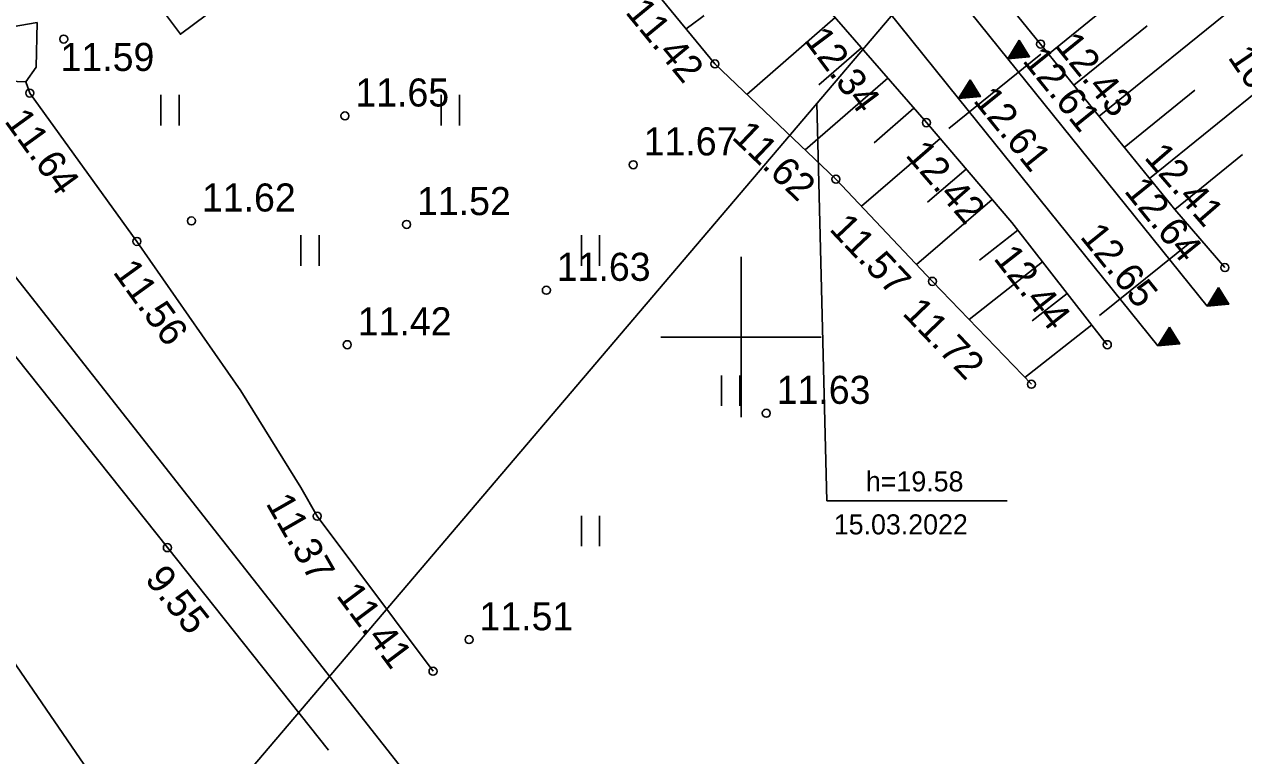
# Model space of a CAD drawing. Extents: x 554198 to 554371, y 6593448 to 6593563.
# Drawn here: x 554282.11 to 554312.55, y 6593489.56 to 6593507.8 of the extents above; entities that cross this region are included whole.
import ezdxf

# ---------------------------------------------------------------- set-up
doc = ezdxf.new("R2010")
doc.units = 0
for name, color, linetype in [('HALJASTUS', 7, 'Continuous'), ('KORGUS-EH2000', 7, 'Continuous'), ('PIIR', 7, 'Continuous'), ('RAJATIS', 7, 'Continuous'), ('RDT', 7, 'Continuous'), ('RELJEEF', 7, 'Continuous'), ('SIOHULIIN', 7, 'Continuous'), ('TEE', 7, 'Continuous'), ('VEEKOGU', 7, 'Continuous'), ('VORK', 7, 'Continuous')]:
    doc.layers.add(name, color=color, linetype=linetype)

msp = doc.modelspace()

# ---------------------------------------------------------------- linework, layer by layer
at = {"layer": 'HALJASTUS'}
for p, q in [((554285.514, 6593506.042), (554285.514, 6593505.28)), ((554285.97, 6593506.042), (554285.97, 6593505.28)), ((554292.514, 6593506.042), (554292.514, 6593505.28)), ((554292.97, 6593506.042), (554292.97, 6593505.28)), ((554289.014, 6593502.542), (554289.014, 6593501.78)), ((554289.47, 6593502.542), (554289.47, 6593501.78)), ((554296.014, 6593502.542), (554296.014, 6593501.78)), ((554296.47, 6593502.542), (554296.47, 6593501.78)), ((554299.514, 6593499.042), (554299.514, 6593498.28)), ((554299.97, 6593499.042), (554299.97, 6593498.28)), ((554296.014, 6593495.542), (554296.014, 6593494.78)), ((554296.47, 6593495.542), (554296.47, 6593494.78))]:
    msp.add_line(p, q, dxfattribs=at)
at = {"layer": 'KORGUS-EH2000'}
for p, q in [((554306.663, 6593506.945), (554306.948, 6593507.41)), ((554306.909, 6593507.346), (554306.871, 6593506.962)), ((554306.939, 6593507.394), (554306.896, 6593506.965)), ((554306.963, 6593507.387), (554306.921, 6593506.967)), ((554306.985, 6593507.351), (554306.947, 6593506.969)), ((554307.207, 6593506.991), (554306.948, 6593507.41)), ((554307.006, 6593507.316), (554306.972, 6593506.971)), ((554306.729, 6593507.052), (554306.719, 6593506.95)), ((554306.759, 6593507.101), (554306.744, 6593506.952)), ((554306.789, 6593507.15), (554306.769, 6593506.954)), ((554306.819, 6593507.199), (554306.795, 6593506.956)), ((554306.849, 6593507.248), (554306.82, 6593506.958)), ((554306.879, 6593507.297), (554306.845, 6593506.96)), ((554307.028, 6593507.281), (554306.997, 6593506.973)), ((554307.049, 6593507.246), (554307.023, 6593506.975)), ((554307.071, 6593507.211), (554307.048, 6593506.977)), ((554307.093, 6593507.176), (554307.073, 6593506.979)), ((554307.114, 6593507.141), (554307.099, 6593506.982)), ((554307.136, 6593507.106), (554307.124, 6593506.984)), ((554307.158, 6593507.07), (554307.149, 6593506.986)), ((554307.179, 6593507.035), (554307.175, 6593506.988)), ((554306.663, 6593506.945), (554307.207, 6593506.991)), ((554306.669, 6593506.955), (554306.668, 6593506.945)), ((554306.699, 6593507.003), (554306.693, 6593506.948)), ((554307.201, 6593507), (554307.2, 6593506.99)), ((554305.433, 6593505.953), (554305.718, 6593506.418)), ((554305.709, 6593506.402), (554305.666, 6593505.973)), ((554305.977, 6593505.999), (554305.718, 6593506.418)), ((554305.529, 6593506.109), (554305.514, 6593505.96)), ((554305.559, 6593506.158), (554305.539, 6593505.962)), ((554305.589, 6593506.207), (554305.565, 6593505.964)), ((554305.619, 6593506.256), (554305.59, 6593505.966)), ((554305.649, 6593506.305), (554305.615, 6593505.968)), ((554305.679, 6593506.354), (554305.641, 6593505.97)), ((554305.733, 6593506.395), (554305.691, 6593505.975)), ((554305.755, 6593506.359), (554305.717, 6593505.977)), ((554305.776, 6593506.324), (554305.742, 6593505.979)), ((554305.798, 6593506.289), (554305.767, 6593505.981)), ((554305.819, 6593506.254), (554305.793, 6593505.983)), ((554305.841, 6593506.219), (554305.818, 6593505.985)), ((554305.863, 6593506.184), (554305.843, 6593505.987)), ((554305.884, 6593506.149), (554305.869, 6593505.99)), ((554305.906, 6593506.114), (554305.894, 6593505.992)), ((554305.433, 6593505.953), (554305.977, 6593505.999)), ((554305.439, 6593505.963), (554305.438, 6593505.953)), ((554305.469, 6593506.011), (554305.463, 6593505.956)), ((554305.499, 6593506.06), (554305.489, 6593505.958)), ((554305.928, 6593506.078), (554305.919, 6593505.994)), ((554305.949, 6593506.043), (554305.945, 6593505.996)), ((554305.971, 6593506.008), (554305.97, 6593505.998)), ((554311.64, 6593500.773), (554311.925, 6593501.238)), ((554312.184, 6593500.819), (554311.925, 6593501.238)), ((554311.736, 6593500.929), (554311.721, 6593500.78)), ((554311.766, 6593500.978), (554311.746, 6593500.782)), ((554311.796, 6593501.027), (554311.772, 6593500.784)), ((554311.826, 6593501.076), (554311.797, 6593500.786)), ((554311.856, 6593501.125), (554311.822, 6593500.788)), ((554311.886, 6593501.174), (554311.848, 6593500.79)), ((554311.916, 6593501.222), (554311.873, 6593500.793)), ((554311.94, 6593501.215), (554311.898, 6593500.795)), ((554311.962, 6593501.179), (554311.924, 6593500.797)), ((554311.983, 6593501.144), (554311.949, 6593500.799)), ((554312.005, 6593501.109), (554311.974, 6593500.801)), ((554312.026, 6593501.074), (554312, 6593500.803)), ((554312.048, 6593501.039), (554312.025, 6593500.805)), ((554312.07, 6593501.004), (554312.05, 6593500.807)), ((554312.091, 6593500.969), (554312.076, 6593500.81)), ((554312.113, 6593500.934), (554312.101, 6593500.812)), ((554311.64, 6593500.773), (554312.184, 6593500.819)), ((554311.646, 6593500.783), (554311.645, 6593500.773)), ((554311.676, 6593500.831), (554311.67, 6593500.776)), ((554311.706, 6593500.88), (554311.696, 6593500.778)), ((554312.135, 6593500.898), (554312.126, 6593500.814)), ((554312.156, 6593500.863), (554312.152, 6593500.816)), ((554312.178, 6593500.828), (554312.177, 6593500.818)), ((554310.41, 6593499.781), (554310.695, 6593500.246)), ((554310.566, 6593500.035), (554310.542, 6593499.792)), ((554310.596, 6593500.084), (554310.567, 6593499.794)), ((554310.626, 6593500.133), (554310.592, 6593499.796)), ((554310.656, 6593500.182), (554310.618, 6593499.798)), ((554310.686, 6593500.23), (554310.643, 6593499.801)), ((554310.71, 6593500.223), (554310.668, 6593499.803)), ((554310.732, 6593500.187), (554310.694, 6593499.805)), ((554310.954, 6593499.827), (554310.695, 6593500.246)), ((554310.753, 6593500.152), (554310.719, 6593499.807)), ((554310.775, 6593500.117), (554310.744, 6593499.809)), ((554310.796, 6593500.082), (554310.77, 6593499.811)), ((554310.818, 6593500.047), (554310.795, 6593499.813)), ((554310.84, 6593500.012), (554310.82, 6593499.815)), ((554310.41, 6593499.781), (554310.954, 6593499.827)), ((554310.416, 6593499.791), (554310.415, 6593499.781)), ((554310.446, 6593499.839), (554310.44, 6593499.784)), ((554310.476, 6593499.888), (554310.466, 6593499.786)), ((554310.506, 6593499.937), (554310.491, 6593499.788)), ((554310.536, 6593499.986), (554310.516, 6593499.79)), ((554310.861, 6593499.977), (554310.846, 6593499.818)), ((554310.883, 6593499.942), (554310.871, 6593499.82)), ((554310.905, 6593499.906), (554310.896, 6593499.822)), ((554310.926, 6593499.871), (554310.922, 6593499.824)), ((554310.948, 6593499.836), (554310.947, 6593499.826))]:
    msp.add_line(p, q, dxfattribs=at)
for centre in [(554283.089, 6593507.435), (554307.48, 6593507.31), (554299.35, 6593506.815), (554282.242, 6593506.088), (554290.11, 6593505.52), (554304.63, 6593505.35), (554297.31, 6593504.3), (554302.37, 6593503.94), (554286.28, 6593502.9), (554291.65, 6593502.81), (554284.916, 6593502.387), (554312.081, 6593501.733), (554295.14, 6593501.17), (554304.78, 6593501.39), (554290.17, 6593499.81), (554309.146, 6593499.81), (554307.25, 6593498.822), (554300.63, 6593498.1), (554289.42, 6593495.53), (554285.677, 6593494.745), (554293.21, 6593492.45), (554292.31, 6593491.66)]:
    msp.add_circle(centre, 0.1, dxfattribs=at)
at = {"layer": 'PIIR'}
msp.add_line((554294.582, 6593485.373), (554263.353, 6593525.033), dxfattribs=at)
at = {"layer": 'RAJATIS'}
msp.add_lwpolyline([(554285.582, 6593508.122), (554285.164, 6593508.682), (554288.636, 6593511.498), (554290.603, 6593513.04), (554291.071, 6593513.244), (554290.979, 6593513.389), (554294.649, 6593516.02), (554295.41, 6593516.667), (554296.041, 6593515.909), (554296.134, 6593515.797), (554295.267, 6593515.075), (554291.81, 6593512.332), (554291.874, 6593512.238), (554291.529, 6593512.003), (554289.23, 6593510.089), (554286.977, 6593508.284), (554286.003, 6593507.557), (554285.582, 6593508.122)], dxfattribs=at)
at = {"layer": 'RDT'}
for p, q in [((554305.188, 6593505.205), (554307.485, 6593507.057)), ((554308.955, 6593500.534), (554311.251, 6593502.386))]:
    msp.add_line(p, q, dxfattribs=at)
for points in [[(554285.824, 6593532.905), (554287.956, 6593530.229), (554292.884, 6593524.093), (554297.103, 6593518.851), (554302.239, 6593512.436), (554306.663, 6593506.945), (554311.64, 6593500.773)], [(554284.588, 6593531.92), (554286.722, 6593529.242), (554291.653, 6593523.103), (554295.871, 6593517.862), (554301.007, 6593511.447), (554305.433, 6593505.953), (554310.41, 6593499.781)]]:
    msp.add_lwpolyline(points, dxfattribs=at)
at = {"layer": 'RELJEEF'}
for p, q in [((554307.68, 6593507.063), (554311.413, 6593510.089)), ((554301.135, 6593509.56), (554298.633, 6593507.688)), ((554308.94, 6593505.51), (554312.527, 6593508.418)), ((554302.349, 6593507.972), (554300.147, 6593506.056)), ((554308.31, 6593506.286), (554310.137, 6593507.767)), ((554303.006, 6593507.217), (554301.94, 6593506.29)), ((554310.199, 6593503.956), (554313.655, 6593506.758)), ((554303.662, 6593506.463), (554301.602, 6593504.671)), ((554309.57, 6593504.733), (554311.33, 6593506.16)), ((554304.318, 6593505.708), (554303.324, 6593504.843)), ((554304.971, 6593504.951), (554303.005, 6593503.269)), ((554310.829, 6593503.179), (554312.524, 6593504.554)), ((554305.621, 6593504.191), (554304.657, 6593503.366)), ((554306.271, 6593503.431), (554304.38, 6593501.813)), ((554306.913, 6593502.664), (554305.955, 6593501.915)), ((554307.529, 6593501.877), (554305.693, 6593500.441)), ((554308.145, 6593501.089), (554307.268, 6593500.403)), ((554308.761, 6593500.302), (554307.087, 6593498.992))]:
    msp.add_line(p, q, dxfattribs=at)
for points in [[(554312.081, 6593501.733), (554310.829, 6593503.179), (554307.48, 6593507.31), (554304.034, 6593511.56), (554302.88, 6593513.07), (554299.553, 6593517.378), (554298.943, 6593517.994)], [(554309.146, 6593499.81), (554306.76, 6593502.86), (554304.63, 6593505.35), (554302.161, 6593508.188), (554298.83, 6593512.64), (554296.962, 6593514.913), (554296.134, 6593515.797)], [(554307.25, 6593498.822), (554304.78, 6593501.39), (554302.37, 6593503.94), (554299.35, 6593506.815), (554296.47, 6593510.32), (554294.416, 6593512.617), (554293.599, 6593513.53), (554293.482, 6593513.659)]]:
    msp.add_lwpolyline(points, dxfattribs=at)
at = {"layer": 'SIOHULIIN'}
for points in [[(554314.701, 6593520.885), (554283.22, 6593483.889)], [(554301.893, 6593505.834), (554302.145, 6593495.916), (554306.643, 6593495.916)]]:
    msp.add_lwpolyline(points, dxfattribs=at)
at = {"layer": 'TEE'}
msp.add_lwpolyline([(554280.554, 6593507.491), (554280.84, 6593507.575), (554282.423, 6593507.849), (554282.4, 6593506.737), (554282.147, 6593506.366), (554281.493, 6593506.397), (554281.123, 6593506.423), (554281.051, 6593506.447), (554280.525, 6593507.42)], close=True, dxfattribs=at)
at = {"layer": 'VEEKOGU'}
for points in [[(554289.699, 6593489.692), (554285.677, 6593494.745), (554279.884, 6593502.023), (554278.226, 6593503.871), (554276.897, 6593505.887), (554273.851, 6593510.088), (554268.23, 6593517.601), (554267.552, 6593518.507)], [(554282.147, 6593506.366), (554282.242, 6593506.088), (554284.916, 6593502.387), (554287.51, 6593498.66), (554289.009, 6593496.248), (554289.42, 6593495.53), (554292.31, 6593491.66)], [(554268.84, 6593476.63), (554268.76, 6593483.17), (554268.99, 6593488.25), (554268.98, 6593490.32), (554268.71, 6593492.39), (554268.728, 6593493.256), (554269.07, 6593493.83), (554270.451, 6593493.847), (554273.152, 6593493.512), (554277.543, 6593495.225), (554278.839, 6593495.787), (554279.67, 6593495.34), (554281.27, 6593492.72), (554283.81, 6593489.03), (554286.14, 6593487.01)]]:
    msp.add_lwpolyline(points, dxfattribs=at)
at = {"layer": 'VORK'}
for p, q in [((554300, 6593502), (554300, 6593498)), ((554298, 6593500), (554302, 6593500))]:
    msp.add_line(p, q, dxfattribs=at)

# ---------------------------------------------------------------- texts
at = {"layer": 'KORGUS-EH2000'}
for s, rotation, p in [(' 11.42 ', 309.4094, (554296.926, 6593508.299)), (' 12.34 ', 306.8039, (554301.4, 6593507.619)), (' 12.43 ', 309.0317, (554307.661, 6593507.457)), (' 12.61 ', 308.8821, (554306.845, 6593507.091)), (' 10.41 ', 304.1926, (554311.994, 6593507.195)), (' 12.61 ', 308.8821, (554305.615, 6593506.099)), (' 11.64 ', 305.8484, (554281.438, 6593505.597)), (' 11.62 ', 316.409, (554299.556, 6593505.141)), (' 12.42 ', 311.0226, (554303.913, 6593504.726)), (' 12.41 ', 310.8872, (554309.876, 6593504.666)), (' 12.64 ', 308.8821, (554309.383, 6593503.841)), (' 11.57 ', 313.3832, (554302.002, 6593502.868)), (' 12.65 ', 308.8821, (554308.281, 6593502.699)), (' 12.44 ', 308.0359, (554306.126, 6593502.163)), (' 11.56 ', 305.8484, (554284.146, 6593501.831)), (' 11.72 ', 313.8856, (554303.825, 6593500.762)), (' 11.37 ', 299.7878, (554287.993, 6593496.077)), (' 9.55 ', 308.5184, (554284.934, 6593494.153)), (' 11.41 ', 306.7513, (554289.719, 6593493.755))]:
    msp.add_text(s, height=0.7, rotation=rotation, dxfattribs=at).set_placement(p)
for s, p in [(' 11.59 ', (554282.75, 6593506.64)), (' 11.65 ', (554290.11, 6593505.753)), (' 11.67 ', (554297.31, 6593504.533)), (' 11.62 ', (554286.28, 6593503.133)), (' 11.52 ', (554291.65, 6593503.043)), (' 11.63 ', (554295.14, 6593501.403)), (' 11.42 ', (554290.17, 6593500.043)), (' 11.63 ', (554300.63, 6593498.333)), (' 11.51 ', (554293.21, 6593492.683))]:
    msp.add_text(s, height=0.7, dxfattribs=at).set_placement(p)
at = {"layer": 'SIOHULIIN'}
for s, p in [('h=19.58', (554303.119, 6593496.148)), ('15.03.2022', (554302.317, 6593495.076))]:
    msp.add_text(s, height=0.5, dxfattribs=at).set_placement(p)

doc.saveas('drawing.dxf')
